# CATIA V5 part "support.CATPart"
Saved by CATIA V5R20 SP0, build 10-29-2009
Part number: support
Bounding box of the stored display mesh (mm): x -60 to 0, y -280 to 70, z -12 to -10
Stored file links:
  C:\Users\thinkmotion1\Desktop\IAO OK\IAO_2010_1458_splanchena\Correction_Khaled\support.CATPart
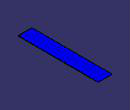
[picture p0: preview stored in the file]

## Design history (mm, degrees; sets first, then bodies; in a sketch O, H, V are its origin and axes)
Body1 (main body)
  Sketch1 on yz-plane, origin (0, 0, 0), H (0, 1, 0), V (0, 0, 1)
    line L1 (-280, -10) -> (70, -10)
    line L2 (70, -10) -> (70, -12)
    line L3 (70, -12) -> (-280, -12)
    line L4 (-280, -12) -> (-280, -10)
    length L4 = 2
    distance H L1 = 10
    length L3 = 350
    horizontal: L1 H, L3 H
    vertical: L2 V, L4 V
    fix: L2
  Pad1: profile Sketch1, direction (-1, 0, 0), length 60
